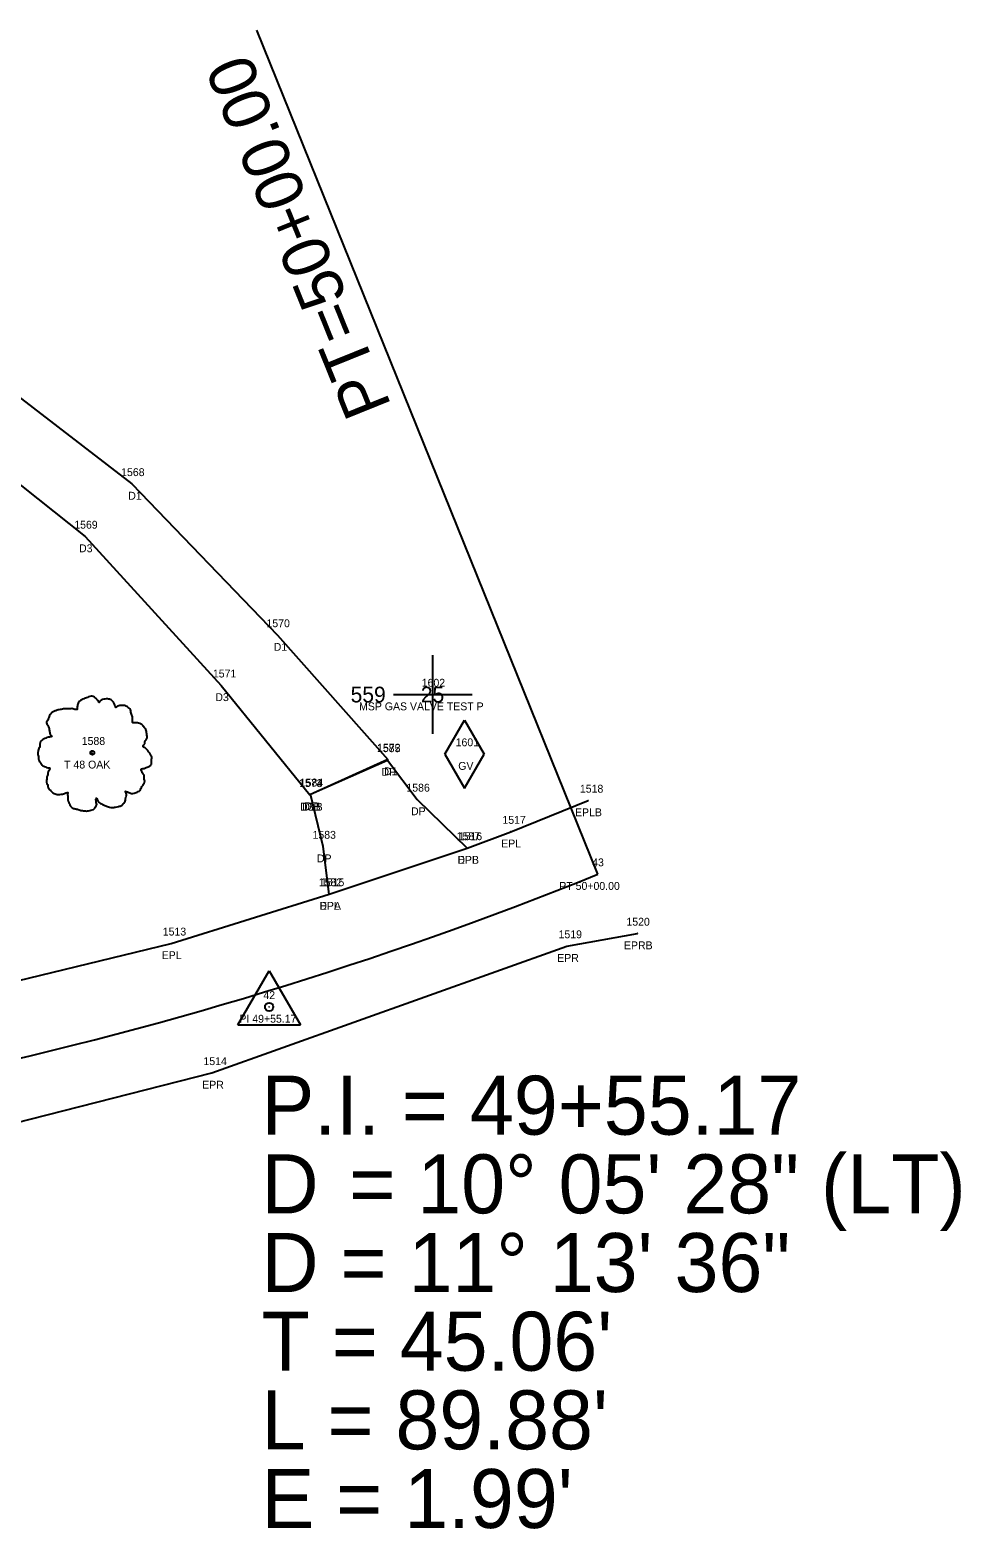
# Model space of a CAD drawing. Extents: x 1965304 to 1970247, y 1117014 to 1118201.
# Drawn here: x 1966698.6 to 1966816.9, y 1117363.8 to 1117555.4 of the extents above; entities that cross this region are included whole.
import ezdxf

# ---------------------------------------------------------------- set-up
doc = ezdxf.new("R2010")
doc.units = 0
for name, color, linetype in [('RD_EX_Driveway', 7, 'Continuous'), ('RD_EX_Driveway_txCode', 7, 'Continuous'), ('RD_EX_Misc', 7, 'Continuous'), ('RD_EX_Misc_txCode', 7, 'Continuous'), ('RD_EX_Road', 7, 'Continuous'), ('RD_EX_Road_txCode', 7, 'Continuous'), ('RD_EX_UT', 7, 'Continuous'), ('RD_EX_UT_txCode', 7, 'Continuous'), ('RD_EX_VEG', 7, 'Continuous'), ('RD_EX_VEG_txCode', 7, 'Continuous'), ('RD_HC_Cl', 7, 'Continuous'), ('RD_HC_Data', 7, 'Continuous'), ('RD_HC_txCode', 7, 'Continuous'), ('RD_SMD_Locator', 7, 'Continuous')]:
    doc.layers.add(name, color=color, linetype=linetype)

msp = doc.modelspace()

# ---------------------------------------------------------------- linework, layer by layer
at = {"layer": 'RD_EX_Driveway'}
for points in [[(1966578.03, 1117435.24), (1966571.58, 1117480.75), (1966567.97, 1117515.31), (1966576.56, 1117516.6), (1966582.11, 1117483.55), (1966603.62, 1117509.1), (1966634.75, 1117528.34), (1966662.08, 1117526.43), (1966689.52, 1117514.66), (1966711.52, 1117497.72), (1966730.01, 1117478.51), (1966744.03, 1117462.69), (1966734.11, 1117458.19)], [(1966589.3, 1117436.33), (1966587.98, 1117456.65), (1966594.08, 1117483.04), (1966609.7, 1117504.07), (1966638.32, 1117518.31), (1966661.32, 1117517.13), (1966685.43, 1117507.04), (1966705.56, 1117491.04), (1966722.87, 1117472.12), (1966734.11, 1117458.19)], [(1966736.6, 1117445.59), (1966735.81, 1117451.62), (1966734.2, 1117458.27), (1966744, 1117462.63), (1966747.77, 1117457.61), (1966754.13, 1117451.44)]]:
    msp.add_lwpolyline(points, dxfattribs=at)
at = {"layer": 'RD_EX_Misc'}
for p, q in [((1966749.75, 1117465.95), (1966749.75, 1117475.95)), ((1966749.75, 1117465.95), (1966749.75, 1117475.95)), ((1966744.75, 1117470.95), (1966754.75, 1117470.95)), ((1966744.75, 1117470.95), (1966754.75, 1117470.95))]:
    msp.add_line(p, q, dxfattribs=at)
at = {"layer": 'RD_EX_Road'}
for points in [[(1966031.82, 1117232.96), (1966074.66, 1117252.15), (1966117.78, 1117271.58), (1966161.06, 1117290.48), (1966205.41, 1117309.23), (1966251.25, 1117327.39), (1966297.25, 1117343.1), (1966344.08, 1117357.04), (1966390.78, 1117368.56), (1966438.12, 1117379.08), (1966484.55, 1117389.13), (1966531.2, 1117398.73), (1966578.39, 1117408.59), (1966604.53, 1117414.06), (1966624.54, 1117418.32), (1966671.32, 1117428.35), (1966716.51, 1117439.32), (1966736.6, 1117445.59), (1966754.13, 1117451.44), (1966759.66, 1117453.52), (1966769.51, 1117457.48)], [(1965729.99, 1117080.3), (1965819.77, 1117119.13), (1965907.74, 1117159.31), (1965995.36, 1117199.04), (1966039.27, 1117218.5), (1966081.24, 1117237.15), (1966124.67, 1117256.55), (1966167.66, 1117275.55), (1966211.47, 1117293.63), (1966257.79, 1117311.58), (1966302.7, 1117327.21), (1966347.9, 1117339.98), (1966394.81, 1117351.64), (1966441.56, 1117361.87), (1966488.62, 1117372.06), (1966534.91, 1117381.34), (1966581.23, 1117390.95), (1966629.53, 1117400.95), (1966675.63, 1117411.11), (1966721.68, 1117422.85), (1966766.8, 1117438.97), (1966775.75, 1117440.57)]]:
    msp.add_lwpolyline(points, dxfattribs=at)
at = {"layer": 'RD_EX_UT'}
for p, q in [((1966751.29, 1117463.38), (1966753.79, 1117467.71)), ((1966751.29, 1117463.38), (1966753.79, 1117467.71)), ((1966753.79, 1117467.71), (1966756.29, 1117463.38)), ((1966753.79, 1117467.71), (1966756.29, 1117463.38)), ((1966751.29, 1117463.38), (1966753.79, 1117459.05)), ((1966751.29, 1117463.38), (1966753.79, 1117459.05)), ((1966753.79, 1117459.05), (1966756.29, 1117463.38)), ((1966753.79, 1117459.05), (1966756.29, 1117463.38))]:
    msp.add_line(p, q, dxfattribs=at)
at = {"layer": 'RD_EX_VEG'}
for centre, radius in [((1966706.49, 1117463.55), 0.25), ((1966706.49, 1117463.55), 0.25), ((1966706.47, 1117463.53), 0.0001), ((1966706.47, 1117463.53), 0.0001)]:
    msp.add_circle(centre, radius, dxfattribs=at)
for points in [[(1966706.62, 1117470.72), (1966706.32, 1117470.74), (1966705.99, 1117470.64), (1966705.74, 1117470.54), (1966705.52, 1117470.47), (1966705.29, 1117470.37), (1966704.99, 1117470.19), (1966704.77, 1117469.99), (1966704.64, 1117469.74), (1966704.59, 1117469.52), (1966704.54, 1117469.25), (1966704.54, 1117469.07), (1966704.42, 1117469.05), (1966704.27, 1117469.07), (1966704.02, 1117469.15), (1966703.77, 1117469.15), (1966703.52, 1117469.15), (1966703.17, 1117469.12), (1966702.82, 1117469.12), (1966702.54, 1117469.07), (1966702.22, 1117469.02), (1966701.84, 1117468.9), (1966701.49, 1117468.77), (1966701.2, 1117468.52), (1966700.95, 1117468.05), (1966700.82, 1117467.7), (1966700.67, 1117467.45), (1966700.82, 1117467), (1966701, 1117466.65), (1966701.02, 1117466.45), (1966701.1, 1117466.02), (1966701.2, 1117465.8), (1966701.32, 1117465.6), (1966701.25, 1117465.57), (1966700.87, 1117465.52), (1966700.57, 1117465.42), (1966700.15, 1117465.2), (1966699.92, 1117464.97), (1966699.82, 1117464.65), (1966699.8, 1117464.3), (1966699.7, 1117464.1), (1966699.62, 1117463.82), (1966699.6, 1117463.75), (1966699.55, 1117463.42), (1966699.65, 1117462.97), (1966699.67, 1117462.62), (1966699.8, 1117462.4), (1966699.95, 1117462.22), (1966700.12, 1117461.97), (1966700.52, 1117461.75), (1966700.85, 1117461.65), (1966701.05, 1117461.62), (1966700.87, 1117461.12), (1966700.82, 1117460.77), (1966700.7, 1117460.37), (1966700.7, 1117460.3), (1966700.65, 1117459.82), (1966700.8, 1117459.5), (1966700.87, 1117459.12), (1966701.05, 1117458.9), (1966701.32, 1117458.6), (1966701.64, 1117458.37), (1966702.14, 1117458.25), (1966702.54, 1117458.27), (1966703.12, 1117458.45), (1966703.37, 1117458.52), (1966703.34, 1117458.35), (1966703.37, 1117457.97), (1966703.37, 1117457.55), (1966703.52, 1117457.23), (1966703.62, 1117456.95), (1966703.77, 1117456.7), (1966704.09, 1117456.48), (1966704.49, 1117456.4), (1966704.92, 1117456.25), (1966705.37, 1117456.18), (1966705.87, 1117456.15), (1966706.47, 1117456.3), (1966706.74, 1117456.43), (1966706.84, 1117456.6), (1966707.04, 1117456.98), (1966706.99, 1117457.2), (1966707.02, 1117457.8), (1966707.12, 1117457.63), (1966707.29, 1117457.28), (1966707.79, 1117456.98), (1966708.19, 1117456.8), (1966708.67, 1117456.65), (1966708.97, 1117456.58), (1966709.44, 1117456.65), (1966709.82, 1117456.73), (1966710.19, 1117456.85), (1966710.49, 1117457.13), (1966710.67, 1117457.4), (1966710.72, 1117457.68), (1966710.79, 1117458.05), (1966710.84, 1117458.22)], [(1966706.62, 1117470.72), (1966706.32, 1117470.74), (1966705.99, 1117470.64), (1966705.74, 1117470.54), (1966705.52, 1117470.47), (1966705.29, 1117470.37), (1966704.99, 1117470.19), (1966704.77, 1117469.99), (1966704.64, 1117469.74), (1966704.59, 1117469.52), (1966704.54, 1117469.25), (1966704.54, 1117469.07), (1966704.42, 1117469.05), (1966704.27, 1117469.07), (1966704.02, 1117469.15), (1966703.77, 1117469.15), (1966703.52, 1117469.15), (1966703.17, 1117469.12), (1966702.82, 1117469.12), (1966702.54, 1117469.07), (1966702.22, 1117469.02), (1966701.84, 1117468.9), (1966701.49, 1117468.77), (1966701.2, 1117468.52), (1966700.95, 1117468.05), (1966700.82, 1117467.7), (1966700.67, 1117467.45), (1966700.82, 1117467), (1966701, 1117466.65), (1966701.02, 1117466.45), (1966701.1, 1117466.02), (1966701.2, 1117465.8), (1966701.32, 1117465.6), (1966701.25, 1117465.57), (1966700.87, 1117465.52), (1966700.57, 1117465.42), (1966700.15, 1117465.2), (1966699.92, 1117464.97), (1966699.82, 1117464.65), (1966699.8, 1117464.3), (1966699.7, 1117464.1), (1966699.62, 1117463.82), (1966699.6, 1117463.75), (1966699.55, 1117463.42), (1966699.65, 1117462.97), (1966699.67, 1117462.62), (1966699.8, 1117462.4), (1966699.95, 1117462.22), (1966700.12, 1117461.97), (1966700.52, 1117461.75), (1966700.85, 1117461.65), (1966701.05, 1117461.62), (1966700.87, 1117461.12), (1966700.82, 1117460.77), (1966700.7, 1117460.37), (1966700.7, 1117460.3), (1966700.65, 1117459.82), (1966700.8, 1117459.5), (1966700.87, 1117459.12), (1966701.05, 1117458.9), (1966701.32, 1117458.6), (1966701.64, 1117458.37), (1966702.14, 1117458.25), (1966702.54, 1117458.27), (1966703.12, 1117458.45), (1966703.37, 1117458.52), (1966703.34, 1117458.35), (1966703.37, 1117457.97), (1966703.37, 1117457.55), (1966703.52, 1117457.23), (1966703.62, 1117456.95), (1966703.77, 1117456.7), (1966704.09, 1117456.48), (1966704.49, 1117456.4), (1966704.92, 1117456.25), (1966705.37, 1117456.18), (1966705.87, 1117456.15), (1966706.47, 1117456.3), (1966706.74, 1117456.43), (1966706.84, 1117456.6), (1966707.04, 1117456.98), (1966706.99, 1117457.2), (1966707.02, 1117457.8), (1966707.12, 1117457.63), (1966707.29, 1117457.28), (1966707.79, 1117456.98), (1966708.19, 1117456.8), (1966708.67, 1117456.65), (1966708.97, 1117456.58), (1966709.44, 1117456.65), (1966709.82, 1117456.73), (1966710.19, 1117456.85), (1966710.49, 1117457.13), (1966710.67, 1117457.4), (1966710.72, 1117457.68), (1966710.79, 1117458.05), (1966710.84, 1117458.22)], [(1966710.84, 1117458.22), (1966710.77, 1117458.4), (1966710.72, 1117458.65), (1966710.79, 1117458.62), (1966710.97, 1117458.57), (1966711.24, 1117458.45), (1966711.47, 1117458.37), (1966711.79, 1117458.4), (1966712.07, 1117458.5), (1966712.52, 1117458.77), (1966712.79, 1117459.25), (1966713.06, 1117459.65), (1966713.14, 1117459.97), (1966713.09, 1117460.2), (1966713.06, 1117460.7), (1966712.86, 1117460.95), (1966712.81, 1117461.07), (1966712.71, 1117461.47), (1966712.79, 1117461.52), (1966713.06, 1117461.57), (1966713.44, 1117461.7), (1966713.71, 1117461.82), (1966713.94, 1117462), (1966714.01, 1117462.22), (1966713.99, 1117462.62), (1966714.04, 1117463.02), (1966713.96, 1117463.17), (1966713.86, 1117463.32), (1966713.79, 1117463.52), (1966713.64, 1117463.67), (1966713.54, 1117463.82), (1966713.44, 1117463.92), (1966713.31, 1117464.07), (1966713.14, 1117464.2), (1966712.99, 1117464.25), (1966712.94, 1117464.4), (1966713.09, 1117464.6), (1966713.14, 1117464.7), (1966713.16, 1117464.92), (1966713.39, 1117465.27), (1966713.44, 1117465.67), (1966713.39, 1117466.1), (1966713.34, 1117466.37), (1966713.19, 1117466.65), (1966712.99, 1117466.9), (1966712.86, 1117467.07), (1966712.69, 1117467.2), (1966712.37, 1117467.32), (1966712.12, 1117467.37), (1966711.77, 1117467.37), (1966711.57, 1117467.42), (1966711.59, 1117467.47), (1966711.59, 1117467.62), (1966711.59, 1117467.9), (1966711.52, 1117468.35), (1966711.37, 1117468.85), (1966711.37, 1117468.87), (1966711.27, 1117469.12), (1966711.04, 1117469.32), (1966710.87, 1117469.42), (1966710.67, 1117469.54), (1966710.42, 1117469.57), (1966710.12, 1117469.57), (1966709.84, 1117469.52), (1966709.64, 1117469.42), (1966709.47, 1117469.3), (1966709.39, 1117469.44), (1966709.29, 1117469.74), (1966709.24, 1117469.89), (1966709.09, 1117470.07), (1966708.87, 1117470.27), (1966708.42, 1117470.39), (1966707.79, 1117470.32), (1966707.49, 1117470.12), (1966707.34, 1117469.94), (1966707.29, 1117470.07), (1966707.09, 1117470.27), (1966706.99, 1117470.44), (1966706.82, 1117470.57), (1966706.67, 1117470.67), (1966706.57, 1117470.72)], [(1966710.84, 1117458.22), (1966710.77, 1117458.4), (1966710.72, 1117458.65), (1966710.79, 1117458.62), (1966710.97, 1117458.57), (1966711.24, 1117458.45), (1966711.47, 1117458.37), (1966711.79, 1117458.4), (1966712.07, 1117458.5), (1966712.52, 1117458.77), (1966712.79, 1117459.25), (1966713.06, 1117459.65), (1966713.14, 1117459.97), (1966713.09, 1117460.2), (1966713.06, 1117460.7), (1966712.86, 1117460.95), (1966712.81, 1117461.07), (1966712.71, 1117461.47), (1966712.79, 1117461.52), (1966713.06, 1117461.57), (1966713.44, 1117461.7), (1966713.71, 1117461.82), (1966713.94, 1117462), (1966714.01, 1117462.22), (1966713.99, 1117462.62), (1966714.04, 1117463.02), (1966713.96, 1117463.17), (1966713.86, 1117463.32), (1966713.79, 1117463.52), (1966713.64, 1117463.67), (1966713.54, 1117463.82), (1966713.44, 1117463.92), (1966713.31, 1117464.07), (1966713.14, 1117464.2), (1966712.99, 1117464.25), (1966712.94, 1117464.4), (1966713.09, 1117464.6), (1966713.14, 1117464.7), (1966713.16, 1117464.92), (1966713.39, 1117465.27), (1966713.44, 1117465.67), (1966713.39, 1117466.1), (1966713.34, 1117466.37), (1966713.19, 1117466.65), (1966712.99, 1117466.9), (1966712.86, 1117467.07), (1966712.69, 1117467.2), (1966712.37, 1117467.32), (1966712.12, 1117467.37), (1966711.77, 1117467.37), (1966711.57, 1117467.42), (1966711.59, 1117467.47), (1966711.59, 1117467.62), (1966711.59, 1117467.9), (1966711.52, 1117468.35), (1966711.37, 1117468.85), (1966711.37, 1117468.87), (1966711.27, 1117469.12), (1966711.04, 1117469.32), (1966710.87, 1117469.42), (1966710.67, 1117469.54), (1966710.42, 1117469.57), (1966710.12, 1117469.57), (1966709.84, 1117469.52), (1966709.64, 1117469.42), (1966709.47, 1117469.3), (1966709.39, 1117469.44), (1966709.29, 1117469.74), (1966709.24, 1117469.89), (1966709.09, 1117470.07), (1966708.87, 1117470.27), (1966708.42, 1117470.39), (1966707.79, 1117470.32), (1966707.49, 1117470.12), (1966707.34, 1117469.94), (1966707.29, 1117470.07), (1966707.09, 1117470.27), (1966706.99, 1117470.44), (1966706.82, 1117470.57), (1966706.67, 1117470.67), (1966706.57, 1117470.72)]]:
    msp.add_spline(points, degree=3, dxfattribs=at)
at = {"layer": 'RD_HC_Cl'}
msp.add_arc((1966579.59, 1117921.32), 510.35, 281.9047, 291.9958, dxfattribs=at)
at = {"layer": 'RD_HC_Data'}
for p, q in [((1966770.74, 1117448.12), (1966727.4, 1117555.41)), ((1966724.99, 1117428.95), (1966728.96, 1117435.83)), ((1966724.99, 1117428.95), (1966728.96, 1117435.83)), ((1966728.96, 1117435.83), (1966732.93, 1117428.95)), ((1966728.96, 1117435.83), (1966732.93, 1117428.95)), ((1966724.99, 1117428.95), (1966732.93, 1117428.95)), ((1966724.99, 1117428.95), (1966732.93, 1117428.95))]:
    msp.add_line(p, q, dxfattribs=at)
msp.add_circle((1966728.96, 1117431.24), 0.529, dxfattribs=at)
msp.add_circle((1966728.96, 1117431.24), 0.529, dxfattribs=at)
at = {"layer": 'RD_SMD_Locator'}
for centre in [(1966711.52, 1117497.72), (1966711.52, 1117497.72), (1966705.56, 1117491.04), (1966705.56, 1117491.04), (1966730.01, 1117478.51), (1966730.01, 1117478.51), (1966722.87, 1117472.12), (1966722.87, 1117472.12), (1966744, 1117462.63), (1966744, 1117462.63), (1966744.03, 1117462.69), (1966744.03, 1117462.69), (1966734.11, 1117458.19), (1966734.11, 1117458.19), (1966734.11, 1117458.19), (1966734.11, 1117458.19), (1966734.2, 1117458.27), (1966734.2, 1117458.27), (1966747.77, 1117457.61), (1966747.77, 1117457.61), (1966769.51, 1117457.48), (1966769.51, 1117457.48), (1966759.66, 1117453.52), (1966759.66, 1117453.52), (1966735.81, 1117451.62), (1966735.81, 1117451.62), (1966754.13, 1117451.44), (1966754.13, 1117451.44), (1966754.13, 1117451.44), (1966754.13, 1117451.44), (1966736.6, 1117445.59), (1966736.6, 1117445.59), (1966736.6, 1117445.59), (1966736.6, 1117445.59), (1966775.75, 1117440.57), (1966775.75, 1117440.57), (1966716.51, 1117439.32), (1966716.51, 1117439.32), (1966766.8, 1117438.97), (1966766.8, 1117438.97), (1966728.96, 1117431.24), (1966728.96, 1117431.24), (1966721.68, 1117422.85), (1966721.68, 1117422.85)]:
    msp.add_circle(centre, 0.001, dxfattribs=at)

# ---------------------------------------------------------------- texts
at = {"layer": 'RD_EX_Driveway_txCode'}
for s, p in [('1568', (1966710.15, 1117498.72)), ('1568', (1966710.15, 1117498.72)), ('D1', (1966711.05, 1117495.72)), ('D1', (1966711.05, 1117495.72)), ('1569', (1966704.19, 1117492.04)), ('1569', (1966704.19, 1117492.04)), ('D3', (1966704.8, 1117489.04)), ('D3', (1966704.8, 1117489.04)), ('1570', (1966728.62, 1117479.51)), ('1570', (1966728.62, 1117479.51)), ('D1', (1966729.54, 1117476.51)), ('D1', (1966729.54, 1117476.51)), ('1571', (1966721.81, 1117473.12)), ('1571', (1966721.81, 1117473.12)), ('D3', (1966722.12, 1117470.12)), ('D3', (1966722.12, 1117470.12)), ('1585', (1966742.66, 1117463.63)), ('1585', (1966742.66, 1117463.63)), ('1572', (1966742.68, 1117463.69)), ('1572', (1966742.68, 1117463.69)), ('DP', (1966743.23, 1117460.63)), ('DP', (1966743.23, 1117460.63)), ('D1', (1966743.56, 1117460.69)), ('D1', (1966743.56, 1117460.69)), ('1573', (1966732.76, 1117459.19)), ('1573', (1966732.76, 1117459.19)), ('1574', (1966732.76, 1117459.19)), ('1574', (1966732.76, 1117459.19)), ('1584', (1966732.85, 1117459.27)), ('1584', (1966732.85, 1117459.27)), ('1586', (1966746.4, 1117458.61)), ('1586', (1966746.4, 1117458.61)), ('D3B', (1966732.88, 1117456.19)), ('D3B', (1966732.88, 1117456.19)), ('D1B', (1966733.16, 1117456.19)), ('D1B', (1966733.16, 1117456.19)), ('DP', (1966733.42, 1117456.27)), ('DP', (1966733.42, 1117456.27)), ('DP', (1966746.99, 1117455.61)), ('DP', (1966746.99, 1117455.61)), ('1583', (1966734.47, 1117452.62)), ('1583', (1966734.47, 1117452.62)), ('1587', (1966752.79, 1117452.44)), ('1587', (1966752.79, 1117452.44)), ('DP', (1966735.03, 1117449.62)), ('DP', (1966735.03, 1117449.62)), ('DPB', (1966752.88, 1117449.44)), ('DPB', (1966752.88, 1117449.44)), ('1582', (1966735.26, 1117446.59)), ('1582', (1966735.26, 1117446.59)), ('DPA', (1966735.34, 1117443.59)), ('DPA', (1966735.34, 1117443.59))]:
    msp.add_text(s, height=1, dxfattribs=at).set_placement(p)
at = {"layer": 'RD_EX_Misc_txCode'}
for s, height, p in [('1602', 1, (1966748.35, 1117471.95)), ('1602', 1, (1966748.35, 1117471.95)), ('559      25 ', 2, (1966739.31, 1117469.95)), ('MSP GAS VALVE TEST P', 1, (1966740.39, 1117468.95)), ('MSP GAS VALVE TEST P', 1, (1966740.39, 1117468.95))]:
    msp.add_text(s, height=height, dxfattribs=at).set_placement(p)
at = {"layer": 'RD_EX_Road_txCode'}
for s, p in [('1518', (1966768.45, 1117458.48)), ('1518', (1966768.45, 1117458.48)), ('EPLB', (1966767.83, 1117455.48)), ('EPLB', (1966767.83, 1117455.48)), ('1517', (1966758.6, 1117454.52)), ('1517', (1966758.6, 1117454.52)), ('1516', (1966753.05, 1117452.44)), ('1516', (1966753.05, 1117452.44)), ('EPL', (1966758.45, 1117451.52)), ('EPL', (1966758.45, 1117451.52)), ('EPL', (1966752.93, 1117449.44)), ('EPL', (1966752.93, 1117449.44)), ('1515', (1966735.54, 1117446.59)), ('1515', (1966735.54, 1117446.59)), ('EPL', (1966735.4, 1117443.59)), ('EPL', (1966735.4, 1117443.59)), ('1520', (1966774.36, 1117441.57)), ('1520', (1966774.36, 1117441.57)), ('1513', (1966715.44, 1117440.32)), ('1513', (1966715.44, 1117440.32)), ('1519', (1966765.74, 1117439.97)), ('1519', (1966765.74, 1117439.97)), ('EPL', (1966715.3, 1117437.32)), ('EPL', (1966715.3, 1117437.32)), ('EPRB', (1966774.05, 1117438.57)), ('EPRB', (1966774.05, 1117438.57)), ('EPR', (1966765.57, 1117436.97)), ('EPR', (1966765.57, 1117436.97)), ('1514', (1966720.61, 1117423.85)), ('1514', (1966720.61, 1117423.85)), ('EPR', (1966720.45, 1117420.85)), ('EPR', (1966720.45, 1117420.85))]:
    msp.add_text(s, height=1, dxfattribs=at).set_placement(p)
at = {"layer": 'RD_EX_UT_txCode'}
for s, p in [('1601', (1966752.66, 1117464.38)), ('1601', (1966752.66, 1117464.38)), ('GV', (1966752.99, 1117461.38)), ('GV', (1966752.99, 1117461.38))]:
    msp.add_text(s, height=1, dxfattribs=at).set_placement(p)
at = {"layer": 'RD_EX_VEG_txCode'}
for s, p in [('1588', (1966705.14, 1117464.55)), ('1588', (1966705.14, 1117464.55)), ('T 48 OAK', (1966702.9, 1117461.55)), ('T 48 OAK', (1966702.9, 1117461.55))]:
    msp.add_text(s, height=1, dxfattribs=at).set_placement(p)
at = {"layer": 'RD_HC_Data'}
msp.add_text('PT=50+00.00', height=6, rotation=111.9958, dxfattribs=at).set_placement((1966744.54, 1117507.64))
for s, p in [('P.I. = 49+55.17', (1966728, 1117415)), ('D', (1966728, 1117405)), ('    = 10%%d 05\' 28" (LT)', (1966728, 1117405)), ('D = 11%%d 13\' 36"', (1966728, 1117395)), ("T = 45.06'", (1966728, 1117385)), ("L = 89.88'", (1966728, 1117375)), ("E = 1.99'", (1966728, 1117365))]:
    msp.add_text(s, height=7.5, dxfattribs=at).set_placement(p)
at = {"layer": 'RD_HC_txCode'}
for s, p in [('43', (1966770.01, 1117449.12)), ('43', (1966770.01, 1117449.12)), ('PT 50+00.00', (1966765.83, 1117446.12)), ('PT 50+00.00', (1966765.83, 1117446.12)), ('42', (1966728.23, 1117432.24)), ('42', (1966728.23, 1117432.24)), ('PI 49+55.17', (1966725.18, 1117429.24)), ('PI 49+55.17', (1966725.18, 1117429.24))]:
    msp.add_text(s, height=1, dxfattribs=at).set_placement(p)

doc.saveas('drawing.dxf')
